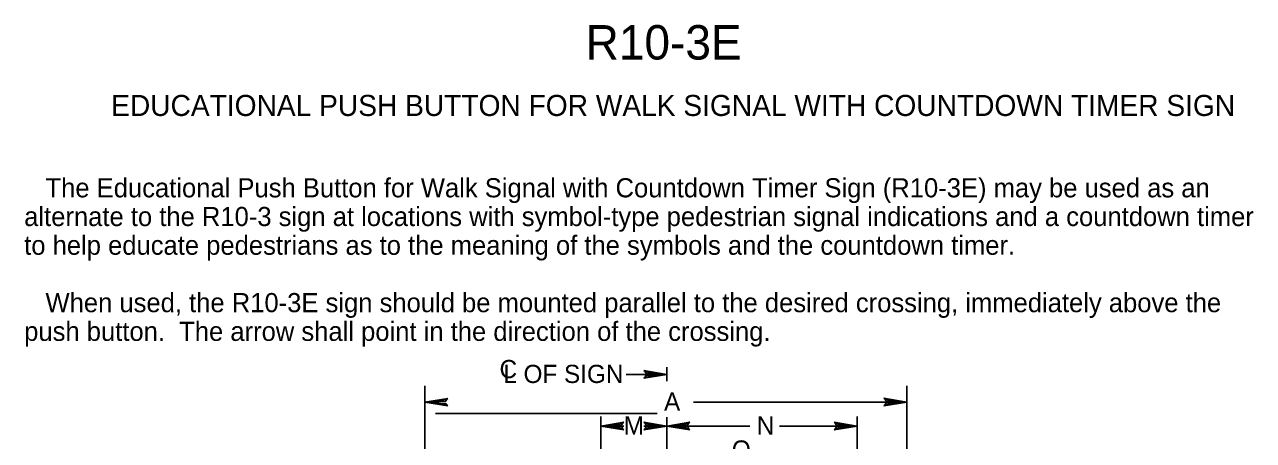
# Model space of a CAD drawing. Extents: x 0.013 to 0.191, y 0.004 to 0.259.
# Drawn here: x 0.0258 to 0.1864, y 0.2048 to 0.2591 of the extents above; entities that cross this region are included whole.
import ezdxf

# ---------------------------------------------------------------- set-up
doc = ezdxf.new("R2010")
doc.units = 0
for name, color, linetype in [('1', 7, 'Continuous'), ('12', 7, 'Continuous'), ('2', 7, 'Continuous'), ('3', 7, 'Continuous')]:
    doc.layers.add(name, color=color, linetype=linetype)

# ---------------------------------------------------------------- blocks, each defined once
blk = doc.blocks.new('RARROW')
at = {"layer": '3'}
for p, q in [((-2.156, 0.285), (-2.2665, 0.384625)), ((-2.2665, 0.384625), (0, 0)), ((0, 0), (-2.2665, -0.379125)), ((-2.156, 0.285), (-2.075625, 0.12075)), ((0, 0), (-2.156, 0.285)), ((-2.14975, -0.2705), (0, 0)), ((-2.075625, 0.12075), (0, 0)), ((0, 0), (-2.074, -0.108)), ((-2.2665, -0.379125), (-2.14975, -0.2705)), ((-2.074, -0.108), (-2.14975, -0.2705))]:
    blk.add_line(p, q, dxfattribs=at)

msp = doc.modelspace()

# ---------------------------------------------------------------- linework, layer by layer
at = {"layer": '1'}
for p, q in [((0.10976, 0.21338), (0.10444, 0.21338)), ((0.07812, 0.21188), (0.07812, 0.1995)), ((0.14113, 0.21188), (0.14113, 0.19987)), ((0.11325, 0.20975), (0.14113, 0.20975)), ((0.0795, 0.20825), (0.1085, 0.20825)), ((0.10113, 0.20788), (0.10113, 0.19125)), ((0.13462, 0.20788), (0.13462, 0.1915)), ((0.10412, 0.20663), (0.10113, 0.20663)), ((0.10975, 0.20663), (0.10675, 0.20663)), ((0.1206, 0.20663), (0.10975, 0.20663)), ((0.13462, 0.20663), (0.12449, 0.20663))]:
    msp.add_line(p, q, dxfattribs=at)
at = {"layer": '12'}
msp.add_line((0.10976, 0.21251), (0.10976, 0.2143), dxfattribs=at)
at = {"layer": '3'}
msp.add_line((0.10975, 0.20778), (0.10975, 0.17364), dxfattribs=at)

# ---------------------------------------------------------------- block references
at = {"layer": '3', "xscale": 0.0013236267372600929, "yscale": 0.001309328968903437}
for p in [(0.10975, 0.21338), (0.14113, 0.20975), (0.10975, 0.20663), (0.13462, 0.20663)]:
    msp.add_blockref('RARROW', p, dxfattribs=at)
at = {"layer": '3', "xscale": 0.0013236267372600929, "yscale": 0.001309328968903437, "rotation": 180}
for p in [(0.07812, 0.20975), (0.10113, 0.20663), (0.10975, 0.20663)]:
    msp.add_blockref('RARROW', p, dxfattribs=at)

# ---------------------------------------------------------------- texts
at = {"layer": '1'}
for s, height, p in [('R10-3E', 0.0045, (0.09913, 0.2545)), ('EDUCATIONAL PUSH BUTTON FOR WALK SIGNAL WITH COUNTDOWN TIMER SIGN', 0.0027503, (0.03712, 0.24713))]:
    msp.add_text(s, height=height, dxfattribs=at).set_placement(p)
at = {"layer": '2'}
for s, height, p in [('   The Educational Push Button for Walk Signal with Countdown Timer Sign (R10-3E) may be used as an', 0.0024998, (0.02575, 0.2365)), ('alternate to the R10-3 sign at locations with symbol-type pedestrian signal indications and a countdown timer', 0.00249975, (0.02575, 0.23275)), ('to help educate pedestrians as to the meaning of the symbols and the countdown timer.', 0.0024998, (0.02575, 0.229)), ('   When used, the R10-3E sign should be mounted parallel to the desired crossing, immediately above the', 0.00249975, (0.02575, 0.2215)), ('push button.  The arrow shall point in the direction of the crossing.', 0.0024998, (0.02575, 0.21775))]:
    msp.add_text(s, height=height, dxfattribs=at).set_placement(p)
at = {"layer": '3'}
for s, height, p in [('C', 0.00238, (0.08788, 0.21288)), ('L OF SIGN', 0.002375, (0.08837, 0.21225)), ('A', 0.00238, (0.10938, 0.20863)), ('M', 0.00238, (0.10412, 0.2055)), ('N', 0.00238, (0.1215, 0.2055)), ('Q', 0.00238, (0.11825, 0.20237))]:
    msp.add_text(s, height=height, dxfattribs=at).set_placement(p)

doc.saveas('drawing.dxf')
